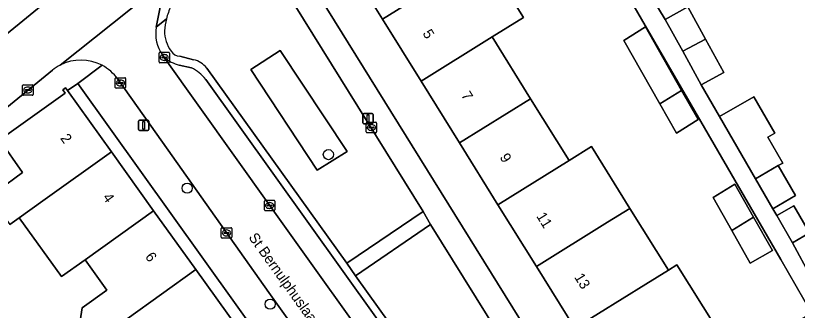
# Model space of a CAD drawing. Extents: x 162523 to 163266, y 381230 to 382050.
# Drawn here: x 162679.2 to 162754.4, y 381834.4 to 381862.7 of the extents above; entities that cross this region are included whole.
import ezdxf

# ---------------------------------------------------------------- set-up
doc = ezdxf.new("R2010")
doc.units = 0
for name, color, linetype in [('IMGEO_Boom', 7, 'Continuous'), ('IMGEO_Erf', 7, 'Continuous'), ('IMGEO_Groenvoorziening', 7, 'Continuous'), ('IMGEO_Kolk', 7, 'Continuous'), ('IMGEO_Lichtmast', 7, 'Continuous'), ('IMGEO_Openbare_ruimte_label', 7, 'Continuous'), ('IMGEO_Pand', 7, 'Continuous'), ('IMGEO_Pand_nummerreeks', 7, 'Continuous'), ('IMGEO_Parkeervlak_open', 7, 'Continuous'), ('IMGEO_Rijbaan_lokaal_open', 7, 'Continuous'), ('IMGEO_Voetpad_gesloten', 7, 'Continuous'), ('IMGEO_Voetpad_open', 7, 'Continuous')]:
    doc.layers.add(name, color=color, linetype=linetype)

msp = doc.modelspace()

# ---------------------------------------------------------------- linework, layer by layer
at = {"layer": 'IMGEO_Boom'}
for centre in [(162709.277, 381849.35), (162695.702, 381846.129), (162703.686, 381834.963)]:
    msp.add_circle(centre, 0.489, dxfattribs=at)
at = {"layer": 'IMGEO_Erf'}
for points in [[(162732.802, 381876.964), (162741.663, 381862.35), (162743.847, 381863.545), (162745.536, 381860.46), (162747.291, 381857.254), (162745.107, 381856.059), (162746.892, 381853.003), (162750.196, 381854.91), (162752.216, 381851.409), (162751.53, 381851.013), (162752.96, 381848.536), (162752.532, 381848.289), (162754.196, 381845.406), (162752.006, 381844.142), (162752.386, 381843.483), (162754.023, 381844.428), (162755.534, 381841.812), (162753.896, 381840.866), (162755.649, 381837.611)], [(162703.711, 381872.133), (162752.202, 381794.074), (162753.849, 381791.703), (162766.887, 381796.3), (162774.478, 381798.601), (162772.186, 381805.655), (162769.657, 381810.036), (162767.262, 381808.65), (162765.58, 381811.556), (162767.975, 381812.942), (162767.323, 381814.077), (162761.902, 381823.466), (162759.129, 381828.269), (162758.953, 381828.164), (162758.554, 381827.926), (162756.86, 381826.917), (162755.075, 381829.911), (162753.392, 381832.737), (162755.485, 381833.984), (162755.731, 381834.13), (162752.78, 381839.267), (162738.115, 381864.612)], [(162724.325, 381868.486), (162728.024, 381862.543), (162725.018, 381860.672), (162728.717, 381854.728), (162732.415, 381848.785), (162734.568, 381850.126), (162738.268, 381844.183), (162741.968, 381838.241), (162742.796, 381838.756), (162746.493, 381832.814), (162750.193, 381826.869), (162749.966, 381826.728), (162753.664, 381820.786), (162750.907, 381819.07), (162754.606, 381813.126)], [(162755.508, 381796.448), (162751.474, 381802.93), (162747.776, 381808.873), (162744.077, 381814.816), (162740.379, 381820.759), (162736.68, 381826.702), (162732.981, 381832.645), (162729.283, 381838.588), (162725.584, 381844.531), (162721.886, 381850.474), (162718.187, 381856.418), (162714.489, 381862.36), (162710.79, 381868.304)], [(162733.516, 381788.621), (162685.191, 381856.189), (162684.204, 381855.513), (162688.419, 381849.626), (162692.477, 381843.958), (162696.534, 381838.291), (162700.591, 381832.623)], [(162677.497, 381845.913), (162679.88, 381847.619), (162677.677, 381850.696)], [(162702.109, 381816.57), (162699.851, 381814.955), (162695.795, 381820.623), (162691.739, 381826.291), (162687.682, 381831.958), (162686.847, 381831.36), (162685.409, 381833.368), (162685.617, 381834.624), (162687.975, 381836.312), (162685.879, 381839.239), (162683.615, 381837.62), (162679.56, 381843.284), (162678.653, 381842.633)]]:
    msp.add_lwpolyline(points, dxfattribs=at)
for points in [[(162737.685, 381860.314), (162739.783, 381861.62), (162743.244, 381855.529), (162744.835, 381852.728), (162742.737, 381851.42), (162741.146, 381854.222)], [(162746.265, 381845.209), (162748.363, 381846.516), (162750.164, 381843.346), (162751.992, 381840.129), (162749.844, 381838.909), (162748.066, 381842.04)]]:
    msp.add_lwpolyline(points, close=True, dxfattribs=at)
at = {"layer": 'IMGEO_Groenvoorziening'}
for points in [[(162697.58, 381857.674), (162711.041, 381838.922), (162718.394, 381843.879), (162703.289, 381868.189)], [(162695.003, 381858.802), (162696.319, 381858.468)]]:
    msp.add_lwpolyline(points, dxfattribs=at)
for points in [[(162708.201, 381847.866), (162711.086, 381849.663), (162704.634, 381859.351), (162701.825, 381857.542)], [(162701.825, 381857.542), (162704.634, 381859.351), (162711.086, 381849.663), (162708.201, 381847.866)], [(162719.105, 381842.623), (162711.887, 381837.703), (162725.214, 381819.087), (162728.423, 381814.491), (162734.234, 381818.334)]]:
    msp.add_lwpolyline(points, close=True, dxfattribs=at)
for centre, radius, start, end in [((162699.967, 381860.809), 6.465, 154.22807, 165.74535), ((162699.668, 381860.921), 6.148, 166.07285, 176.77668), ((162696.653, 381861.192), 3.123, 178.62426, 217.02868), ((162695.08, 381859.884), 1.085, 211.88283, 265.93044), ((162695.822, 381856.281), 2.243, 38.40309, 77.20303)]:
    msp.add_arc(centre, radius, start, end, dxfattribs=at)
at = {"layer": 'IMGEO_Kolk'}
for p, q in [((162692.999, 381858.263), (162692.999, 381859.115)), ((162693.074, 381859.189), (162693.926, 381859.189)), ((162693.258, 381858.683), (162693.258, 381858.695)), ((162693.301, 381858.732), (162693.699, 381858.732)), ((162693.487, 381858.969), (162693.512, 381858.969)), ((162693.742, 381858.695), (162693.742, 381858.683)), ((162694, 381859.115), (162694, 381858.263)), ((162693.926, 381858.189), (162693.074, 381858.189)), ((162693.696, 381858.646), (162693.298, 381858.646)), ((162693.51, 381858.409), (162693.485, 381858.409)), ((162688.786, 381855.812), (162688.786, 381856.664)), ((162688.861, 381856.738), (162689.713, 381856.738)), ((162689.274, 381856.518), (162689.299, 381856.518)), ((162689.787, 381856.664), (162689.787, 381855.812)), ((162679.884, 381855.129), (162679.884, 381855.981)), ((162679.959, 381856.055), (162680.811, 381856.055)), ((162680.372, 381855.835), (162680.397, 381855.835)), ((162680.885, 381855.981), (162680.885, 381855.129)), ((162689.713, 381855.738), (162688.861, 381855.738)), ((162689.045, 381856.232), (162689.045, 381856.244)), ((162689.483, 381856.195), (162689.085, 381856.195)), ((162689.088, 381856.281), (162689.486, 381856.281)), ((162689.297, 381855.958), (162689.272, 381855.958)), ((162689.529, 381856.244), (162689.529, 381856.232)), ((162680.811, 381855.055), (162679.959, 381855.055)), ((162680.143, 381855.549), (162680.143, 381855.561)), ((162680.581, 381855.512), (162680.183, 381855.512)), ((162680.186, 381855.598), (162680.584, 381855.598)), ((162680.395, 381855.275), (162680.37, 381855.275)), ((162680.627, 381855.561), (162680.627, 381855.549)), ((162712.91, 381851.527), (162712.91, 381852.379)), ((162712.985, 381852.453), (162713.837, 381852.453)), ((162713.169, 381851.947), (162713.169, 381851.959)), ((162713.607, 381851.91), (162713.209, 381851.91)), ((162713.212, 381851.996), (162713.61, 381851.996)), ((162713.398, 381852.233), (162713.423, 381852.233)), ((162713.653, 381851.959), (162713.653, 381851.947)), ((162713.911, 381852.379), (162713.911, 381851.527)), ((162713.837, 381851.453), (162712.985, 381851.453)), ((162713.421, 381851.673), (162713.396, 381851.673)), ((162703.13, 381844.028), (162703.13, 381844.88)), ((162703.205, 381844.954), (162704.057, 381844.954)), ((162703.389, 381844.448), (162703.389, 381844.46)), ((162703.827, 381844.411), (162703.429, 381844.411)), ((162703.432, 381844.497), (162703.83, 381844.497)), ((162703.618, 381844.734), (162703.643, 381844.734)), ((162703.873, 381844.46), (162703.873, 381844.448)), ((162704.131, 381844.88), (162704.131, 381844.028)), ((162704.057, 381843.954), (162703.205, 381843.954)), ((162703.641, 381844.174), (162703.616, 381844.174)), ((162698.982, 381841.396), (162698.982, 381842.248)), ((162699.057, 381842.322), (162699.909, 381842.322)), ((162699.983, 381842.248), (162699.983, 381841.396)), ((162699.241, 381841.816), (162699.241, 381841.828)), ((162699.679, 381841.779), (162699.281, 381841.779)), ((162699.284, 381841.865), (162699.682, 381841.865)), ((162699.493, 381841.542), (162699.468, 381841.542)), ((162699.47, 381842.102), (162699.495, 381842.102)), ((162699.725, 381841.828), (162699.725, 381841.816)), ((162699.909, 381841.322), (162699.057, 381841.322))]:
    msp.add_line(p, q, dxfattribs=at)
for points in [[(162692.999, 381858.263), (162692.999, 381859.115)], [(162693.074, 381859.189), (162693.926, 381859.189)], [(162694, 381859.115), (162694, 381858.263)], [(162693.926, 381858.189), (162693.074, 381858.189)], [(162688.786, 381855.812), (162688.786, 381856.664)], [(162688.861, 381856.738), (162689.713, 381856.738)], [(162689.787, 381856.664), (162689.787, 381855.812)], [(162679.884, 381855.129), (162679.884, 381855.981)], [(162679.959, 381856.055), (162680.811, 381856.055)], [(162680.885, 381855.981), (162680.885, 381855.129)], [(162689.713, 381855.738), (162688.861, 381855.738)], [(162680.811, 381855.055), (162679.959, 381855.055)], [(162712.91, 381851.527), (162712.91, 381852.379)], [(162712.985, 381852.453), (162713.837, 381852.453)], [(162713.911, 381852.379), (162713.911, 381851.527)], [(162713.837, 381851.453), (162712.985, 381851.453)], [(162703.13, 381844.028), (162703.13, 381844.88)], [(162703.205, 381844.954), (162704.057, 381844.954)], [(162704.131, 381844.88), (162704.131, 381844.028)], [(162704.057, 381843.954), (162703.205, 381843.954)], [(162698.982, 381841.396), (162698.982, 381842.248)], [(162699.057, 381842.322), (162699.909, 381842.322)], [(162699.983, 381842.248), (162699.983, 381841.396)], [(162699.909, 381841.322), (162699.057, 381841.322)]]:
    msp.add_lwpolyline(points, dxfattribs=at)
for centre, radius, start, end in [((162693.076, 381859.113), 0.0765, 91.55205, 178.44795), ((162693.076, 381859.113), 0.0765, 91.55205, 178.44795), ((162693.298, 381858.692), 0.0403, 85.87752, 175.75265), ((162693.295, 381858.682), 0.0366, 178.93798, 274.71019), ((162693.699, 381858.689), 0.043, 264.86636, 352.45326), ((162693.703, 381858.694), 0.0386, 1.73085, 96.63898), ((162693.924, 381859.113), 0.0765, 1.55205, 88.44795), ((162693.924, 381859.113), 0.0765, 1.55205, 88.44795), ((162693.076, 381858.265), 0.0765, 181.55205, 268.44795), ((162693.076, 381858.265), 0.0765, 181.55205, 268.44795), ((162693.924, 381858.265), 0.0765, 271.55205, 358.44795), ((162693.924, 381858.265), 0.0765, 271.55205, 358.44795), ((162688.863, 381856.662), 0.0765, 91.55205, 178.44795), ((162688.863, 381856.662), 0.0765, 91.55205, 178.44795), ((162689.711, 381856.662), 0.0765, 1.55205, 88.44795), ((162689.711, 381856.662), 0.0765, 1.55205, 88.44795), ((162679.961, 381855.979), 0.0765, 91.55205, 178.44795), ((162679.961, 381855.979), 0.0765, 91.55205, 178.44795), ((162680.809, 381855.979), 0.0765, 1.55205, 88.44795), ((162680.809, 381855.979), 0.0765, 1.55205, 88.44795), ((162688.863, 381855.814), 0.0765, 181.55205, 268.44795), ((162688.863, 381855.814), 0.0765, 181.55205, 268.44795), ((162689.085, 381856.241), 0.0403, 85.87752, 175.75265), ((162689.082, 381856.231), 0.0366, 178.93798, 274.71019), ((162689.486, 381856.238), 0.043, 264.86636, 352.45326), ((162689.49, 381856.243), 0.0386, 1.73085, 96.63898), ((162689.711, 381855.814), 0.0765, 271.55205, 358.44795), ((162689.711, 381855.814), 0.0765, 271.55205, 358.44795), ((162679.961, 381855.131), 0.0765, 181.55205, 268.44795), ((162679.961, 381855.131), 0.0765, 181.55205, 268.44795), ((162680.183, 381855.558), 0.0403, 85.87752, 175.75265), ((162680.18, 381855.548), 0.0366, 178.93798, 274.71019), ((162680.584, 381855.555), 0.043, 264.86636, 352.45326), ((162680.588, 381855.56), 0.0386, 1.73085, 96.63898), ((162680.809, 381855.131), 0.0765, 271.55205, 358.44795), ((162680.809, 381855.131), 0.0765, 271.55205, 358.44795), ((162712.987, 381852.377), 0.0765, 91.55205, 178.44795), ((162712.987, 381852.377), 0.0765, 91.55205, 178.44795), ((162713.209, 381851.956), 0.0403, 85.87752, 175.75265), ((162713.206, 381851.946), 0.0366, 178.93798, 274.71019), ((162713.61, 381851.953), 0.043, 264.86636, 352.45326), ((162713.614, 381851.958), 0.0386, 1.73085, 96.63898), ((162713.835, 381852.377), 0.0765, 1.55205, 88.44795), ((162713.835, 381852.377), 0.0765, 1.55205, 88.44795), ((162712.987, 381851.529), 0.0765, 181.55205, 268.44795), ((162712.987, 381851.529), 0.0765, 181.55205, 268.44795), ((162713.835, 381851.529), 0.0765, 271.55205, 358.44795), ((162713.835, 381851.529), 0.0765, 271.55205, 358.44795), ((162703.207, 381844.878), 0.0765, 91.55205, 178.44795), ((162703.207, 381844.878), 0.0765, 91.55205, 178.44795), ((162703.429, 381844.457), 0.0403, 85.87752, 175.75265), ((162703.426, 381844.447), 0.0366, 178.93798, 274.71019), ((162703.83, 381844.454), 0.043, 264.86636, 352.45326), ((162703.834, 381844.459), 0.0386, 1.73085, 96.63898), ((162704.055, 381844.878), 0.0765, 1.55205, 88.44795), ((162704.055, 381844.878), 0.0765, 1.55205, 88.44795), ((162703.207, 381844.03), 0.0765, 181.55205, 268.44795), ((162703.207, 381844.03), 0.0765, 181.55205, 268.44795), ((162704.055, 381844.03), 0.0765, 271.55205, 358.44795), ((162704.055, 381844.03), 0.0765, 271.55205, 358.44795), ((162699.059, 381842.246), 0.0765, 91.55205, 178.44795), ((162699.059, 381842.246), 0.0765, 91.55205, 178.44795), ((162699.907, 381842.246), 0.0765, 1.55205, 88.44795), ((162699.907, 381842.246), 0.0765, 1.55205, 88.44795), ((162699.059, 381841.398), 0.0765, 181.55205, 268.44795), ((162699.059, 381841.398), 0.0765, 181.55205, 268.44795), ((162699.281, 381841.825), 0.0403, 85.87752, 175.75265), ((162699.278, 381841.815), 0.0366, 178.93798, 274.71019), ((162699.682, 381841.822), 0.043, 264.86636, 352.45326), ((162699.686, 381841.827), 0.0386, 1.73085, 96.63898), ((162699.907, 381841.398), 0.0765, 271.55205, 358.44795), ((162699.907, 381841.398), 0.0765, 271.55205, 358.44795)]:
    msp.add_arc(centre, radius, start, end, dxfattribs=at)
for centre, major_axis, ratio, start_param, end_param in [((162693.486, 381858.689), (-0.387, 0.002), 0.722429, 4.712389, 7.853982), ((162693.511, 381858.689), (-0.39, 0.002), 0.717154, 1.570796, 4.712389), ((162689.273, 381856.238), (-0.387, 0.002), 0.722429, 4.712389, 7.853982), ((162689.298, 381856.238), (-0.39, 0.002), 0.717154, 1.570796, 4.712389), ((162680.371, 381855.555), (-0.387, 0.002), 0.722429, 4.712389, 7.853982), ((162680.396, 381855.555), (-0.39, 0.002), 0.717154, 1.570796, 4.712389), ((162713.397, 381851.953), (-0.387, 0.002), 0.722429, 4.712389, 7.853982), ((162713.422, 381851.953), (-0.39, 0.002), 0.717154, 1.570796, 4.712389), ((162703.617, 381844.454), (-0.387, 0.002), 0.722429, 4.712389, 7.853982), ((162703.642, 381844.454), (-0.39, 0.002), 0.717154, 1.570796, 4.712389), ((162699.469, 381841.822), (-0.387, 0.002), 0.722429, 4.712389, 7.853982), ((162699.494, 381841.822), (-0.39, 0.002), 0.717154, 1.570796, 4.712389)]:
    msp.add_ellipse(centre, major_axis=major_axis, ratio=ratio, start_param=start_param, end_param=end_param, dxfattribs=at)
at = {"layer": 'IMGEO_Lichtmast'}
for p, q in [((162691.128, 381852.668), (162691.918, 381852.668)), ((162691.918, 381852.668), (162691.128, 381852.668)), ((162712.595, 381852.407), (162712.595, 381853.207)), ((162712.595, 381853.207), (162712.595, 381852.407)), ((162712.695, 381853.307), (162713.485, 381853.307)), ((162713.485, 381853.307), (162712.695, 381853.307)), ((162713.585, 381853.207), (162713.585, 381852.407)), ((162713.585, 381852.407), (162713.585, 381853.207)), ((162691.028, 381851.768), (162691.028, 381852.568)), ((162691.028, 381852.568), (162691.028, 381851.768)), ((162692.018, 381852.568), (162692.018, 381851.768)), ((162692.018, 381851.768), (162692.018, 381852.568)), ((162713.485, 381852.307), (162712.695, 381852.307)), ((162712.695, 381852.307), (162713.485, 381852.307)), ((162691.918, 381851.668), (162691.128, 381851.668)), ((162691.128, 381851.668), (162691.918, 381851.668))]:
    msp.add_line(p, q, dxfattribs=at)
for points in [[(162713.015, 381853.182), (162713.165, 381853.182), (162713.165, 381852.432), (162713.015, 381852.432), (162713.015, 381853.182)], [(162691.448, 381852.543), (162691.598, 381852.543), (162691.598, 381851.793), (162691.448, 381851.793), (162691.448, 381852.543)]]:
    msp.add_lwpolyline(points, dxfattribs=at)
for centre, start, end in [((162691.128, 381852.568), 90, 180), ((162691.128, 381852.568), 90, 180), ((162691.918, 381852.568), 0, 90), ((162691.918, 381852.568), 360, 90), ((162712.695, 381853.207), 90, 180), ((162712.695, 381853.207), 90, 180), ((162713.485, 381853.207), 0, 90), ((162713.485, 381853.207), 360, 90), ((162712.695, 381852.407), 180, 270), ((162712.695, 381852.407), 180, 270), ((162713.485, 381852.407), 270, 0), ((162713.485, 381852.407), 270, 0), ((162691.128, 381851.768), 180, 270), ((162691.128, 381851.768), 180, 270), ((162691.918, 381851.768), 270, 0), ((162691.918, 381851.768), 270, 0)]:
    msp.add_arc(centre, 0.1, start, end, dxfattribs=at)
at = {"layer": 'IMGEO_Pand'}
for points in [[(162724.325, 381868.486), (162720.626, 381874.429), (162717.621, 381872.559), (162710.79, 381868.304), (162714.489, 381862.36)], [(162718.187, 381856.418), (162725.018, 381860.672), (162728.024, 381862.543), (162724.325, 381868.486), (162714.489, 381862.36)], [(162745.536, 381860.46), (162743.847, 381863.545), (162741.663, 381862.35), (162743.343, 381859.281)], [(162739.783, 381861.62), (162737.685, 381860.314), (162741.146, 381854.222), (162743.244, 381855.529)], [(162718.187, 381856.418), (162721.886, 381850.474), (162728.717, 381854.728), (162725.018, 381860.672)], [(162745.536, 381860.46), (162743.343, 381859.281), (162745.107, 381856.059), (162747.291, 381857.254)], [(162684.204, 381855.513), (162684.019, 381855.771), (162683.733, 381855.567), (162683.96, 381855.25), (162677.922, 381850.928), (162677.693, 381851.248), (162677.421, 381851.053), (162677.677, 381850.696), (162679.88, 381847.619), (162677.497, 381845.913), (162677.25, 381844.593), (162678.653, 381842.633), (162679.56, 381843.284), (162681.822, 381844.906), (162688.419, 381849.626)], [(162744.835, 381852.728), (162743.244, 381855.529), (162741.146, 381854.222), (162742.737, 381851.42)], [(162750.342, 381847.025), (162752.532, 381848.289), (162752.96, 381848.536), (162751.53, 381851.013), (162752.216, 381851.409), (162750.196, 381854.91), (162746.892, 381853.003)], [(162725.584, 381844.531), (162732.415, 381848.785), (162728.717, 381854.728), (162721.886, 381850.474)], [(162725.584, 381844.531), (162729.283, 381838.588), (162736.114, 381842.842), (162738.268, 381844.183), (162734.568, 381850.126), (162732.415, 381848.785)], [(162688.419, 381849.626), (162681.822, 381844.906), (162679.56, 381843.284), (162683.615, 381837.62), (162685.879, 381839.239), (162692.477, 381843.958)], [(162752.532, 381848.289), (162750.342, 381847.025), (162752.006, 381844.142), (162754.196, 381845.406)], [(162748.363, 381846.516), (162746.265, 381845.209), (162748.066, 381842.04), (162750.164, 381843.346)], [(162752.386, 381843.483), (162753.896, 381840.866), (162755.534, 381841.812), (162754.023, 381844.428)], [(162696.534, 381838.291), (162692.477, 381843.958), (162685.879, 381839.239), (162687.975, 381836.312), (162685.617, 381834.624), (162685.409, 381833.368), (162686.847, 381831.36), (162687.682, 381831.958), (162689.937, 381833.572)], [(162741.968, 381838.241), (162738.268, 381844.183), (162736.114, 381842.842), (162729.283, 381838.588), (162732.981, 381832.645), (162739.812, 381836.899)], [(162750.164, 381843.346), (162748.066, 381842.04), (162749.844, 381838.909), (162751.992, 381840.129)], [(162742.796, 381838.756), (162741.968, 381838.241), (162739.812, 381836.899), (162732.981, 381832.645), (162736.68, 381826.702), (162746.493, 381832.814)], [(162696.534, 381838.291), (162689.937, 381833.572), (162687.682, 381831.958), (162691.739, 381826.291), (162693.994, 381827.904), (162700.591, 381832.623)]]:
    msp.add_lwpolyline(points, close=True, dxfattribs=at)
at = {"layer": 'IMGEO_Parkeervlak_open'}
for points in [[(162693.495, 381858.692), (162703.613, 381844.475), (162715.566, 381827.76), (162728.313, 381810.023), (162740.722, 381792.594)], [(162696.126, 381857.706), (162694.921, 381857.95)], [(162740.249, 381796.81), (162697.482, 381856.586)]]:
    msp.add_lwpolyline(points, dxfattribs=at)
for centre, radius, start, end in [((162696.031, 381861.825), 4.031, 231.00807, 254.01271), ((162694.166, 381853.952), 4.234, 38.45898, 62.43042)]:
    msp.add_arc(centre, radius, start, end, dxfattribs=at)
at = {"layer": 'IMGEO_Rijbaan_lokaal_open'}
for points in [[(162695.216, 381867.785), (162698.457, 381870.411), (162694.996, 381874.59), (162688.855, 381869.619), (162681.316, 381863.363), (162672.848, 381856.46), (162665.027, 381850.088), (162661.191, 381846.959), (162656.652, 381843.257), (162653.131, 381840.384), (162648.579, 381836.677), (162642.953, 381831.956), (162646.101, 381827.394), (162660.46, 381839.32), (162661.37, 381840.059), (162668.127, 381845.543), (162676.395, 381852.319)], [(162692.733, 381861.594), (162693.061, 381863.379), (162693.54, 381865.99), (162683.487, 381857.957)], [(162683.487, 381857.957), (162693.54, 381865.99)], [(162728.313, 381810.023), (162715.566, 381827.76), (162703.613, 381844.475), (162693.495, 381858.692), (162693.324, 381858.932)], [(162676.395, 381852.319), (162682.745, 381857.472)], [(162689.021, 381856.614), (162693.329, 381850.547), (162703.538, 381836.077), (162719.288, 381814.036), (162729.638, 381799.644), (162737.359, 381788.833), (162740.416, 381785.225)]]:
    msp.add_lwpolyline(points, dxfattribs=at)
for centre, radius, start, end in [((162696.18, 381860.963), 3.504, 169.62157, 215.41326), ((162685.403, 381854.216), 4.203, 117.11688, 129.2235), ((162685.482, 381854.097), 4.345, 62.01817, 117.32833), ((162685.462, 381854.08), 4.369, 35.44709, 61.89522)]:
    msp.add_arc(centre, radius, start, end, dxfattribs=at)
at = {"layer": 'IMGEO_Voetpad_gesloten'}
msp.add_lwpolyline([(162672.848, 381856.46), (162681.316, 381863.363), (162688.855, 381869.619), (162694.996, 381874.59), (162695.513, 381875.009), (162700.595, 381879.197), (162702.789, 381880.999), (162705.831, 381883.214), (162710.772, 381886.8), (162712.639, 381888.043), (162716.347, 381890.607), (162731.552, 381900.569), (162746.002, 381909.969), (162753.541, 381914.762), (162754.588, 381915.413), (162760.8, 381919.183)], dxfattribs=at)
at = {"layer": 'IMGEO_Voetpad_open'}
for points in [[(162755.649, 381837.611), (162753.896, 381840.866), (162752.386, 381843.483), (162752.006, 381844.142), (162750.342, 381847.025), (162746.892, 381853.003), (162745.107, 381856.059), (162743.343, 381859.281), (162741.663, 381862.35), (162732.802, 381876.964)], [(162747.925, 381792.231), (162752.202, 381794.074), (162703.711, 381872.133)], [(162703.289, 381868.189), (162718.394, 381843.879), (162719.105, 381842.623), (162734.234, 381818.334), (162734.998, 381817.128), (162747.87, 381796.391)], [(162693.54, 381865.99), (162693.061, 381863.379), (162692.733, 381861.594), (162693.701, 381862.401)], [(162738.115, 381864.612), (162752.78, 381839.267), (162755.731, 381834.13)], [(162693.701, 381862.401), (162692.733, 381861.594)], [(162693.324, 381858.932), (162693.495, 381858.692)], [(162696.319, 381858.468), (162695.003, 381858.802)], [(162663.076, 381838.336), (162665.786, 381840.593), (162666.869, 381841.547), (162666.996, 381841.659), (162669.496, 381843.741), (162677.677, 381850.696), (162677.421, 381851.053), (162677.693, 381851.248), (162677.922, 381850.928), (162683.96, 381855.25), (162683.733, 381855.567), (162684.019, 381855.771), (162684.204, 381855.513), (162685.191, 381856.189), (162687.52, 381857.934)], [(162687.52, 381857.934), (162685.191, 381856.189), (162733.516, 381788.621)], [(162694.921, 381857.95), (162696.126, 381857.706)], [(162682.745, 381857.472), (162676.395, 381852.319), (162668.127, 381845.543), (162668.442, 381845.156), (162661.685, 381839.672), (162661.37, 381840.059), (162660.46, 381839.32), (162646.101, 381827.394), (162646.757, 381824.316), (162648.917, 381826.314), (162648.679, 381826.587), (162648.928, 381826.805), (162649.184, 381826.51), (162654.779, 381831.382), (162654.506, 381831.695), (162654.782, 381831.936), (162655.084, 381831.589), (162657.279, 381833.5), (162663.076, 381838.336)], [(162740.762, 381797.112), (162733.079, 381807.822), (162729.229, 381813.337), (162728.423, 381814.491), (162725.214, 381819.087), (162711.887, 381837.703), (162711.041, 381838.922), (162697.58, 381857.674)], [(162693.329, 381850.547), (162689.021, 381856.614)], [(162697.482, 381856.586), (162740.249, 381796.81)], [(162740.416, 381785.225), (162737.359, 381788.833), (162729.638, 381799.644), (162719.288, 381814.036), (162703.538, 381836.077), (162693.329, 381850.547)]]:
    msp.add_lwpolyline(points, dxfattribs=at)
msp.add_lwpolyline([(162711.887, 381837.703), (162719.105, 381842.623), (162718.394, 381843.879), (162711.041, 381838.922)], close=True, dxfattribs=at)
for centre, radius, start, end in [((162699.967, 381860.809), 6.465, 154.22807, 165.74535), ((162699.668, 381860.921), 6.148, 166.07285, 176.77668), ((162696.18, 381860.963), 3.504, 169.62157, 215.41326), ((162696.653, 381861.192), 3.123, 178.62426, 217.02868), ((162696.031, 381861.825), 4.031, 231.00807, 254.01271), ((162695.08, 381859.884), 1.085, 211.88283, 265.93044), ((162685.403, 381854.216), 4.203, 117.11688, 129.2235), ((162685.482, 381854.097), 4.345, 62.01817, 117.32833), ((162685.462, 381854.08), 4.369, 35.44709, 61.89522), ((162695.822, 381856.281), 2.243, 38.40309, 77.20303), ((162694.166, 381853.952), 4.234, 38.45898, 62.43042)]:
    msp.add_arc(centre, radius, start, end, dxfattribs=at)

# ---------------------------------------------------------------- texts
at = {"layer": 'IMGEO_Openbare_ruimte_label'}
msp.add_text('St Bernulphuslaan', height=1, rotation=305.5177, dxfattribs=at).set_placement((162701.562, 381841.389))
at = {"layer": 'IMGEO_Pand_nummerreeks'}
for s, rotation, p in [('5', 301.89516, (162718.296, 381861.012)), ('7', 301.89516, (162722.004, 381855.054)), ('2', 305.60339, (162683.456, 381850.922)), ('9', 301.89516, (162725.712, 381849.096)), ('4', 305.60339, (162687.535, 381845.223)), ('11', 301.89516, (162729.236, 381843.433)), ('6', 305.60339, (162691.614, 381839.527)), ('13', 301.89635, (162732.883, 381837.571))]:
    msp.add_text(s, height=1, rotation=rotation, dxfattribs=at).set_placement(p)

doc.saveas('drawing.dxf')
